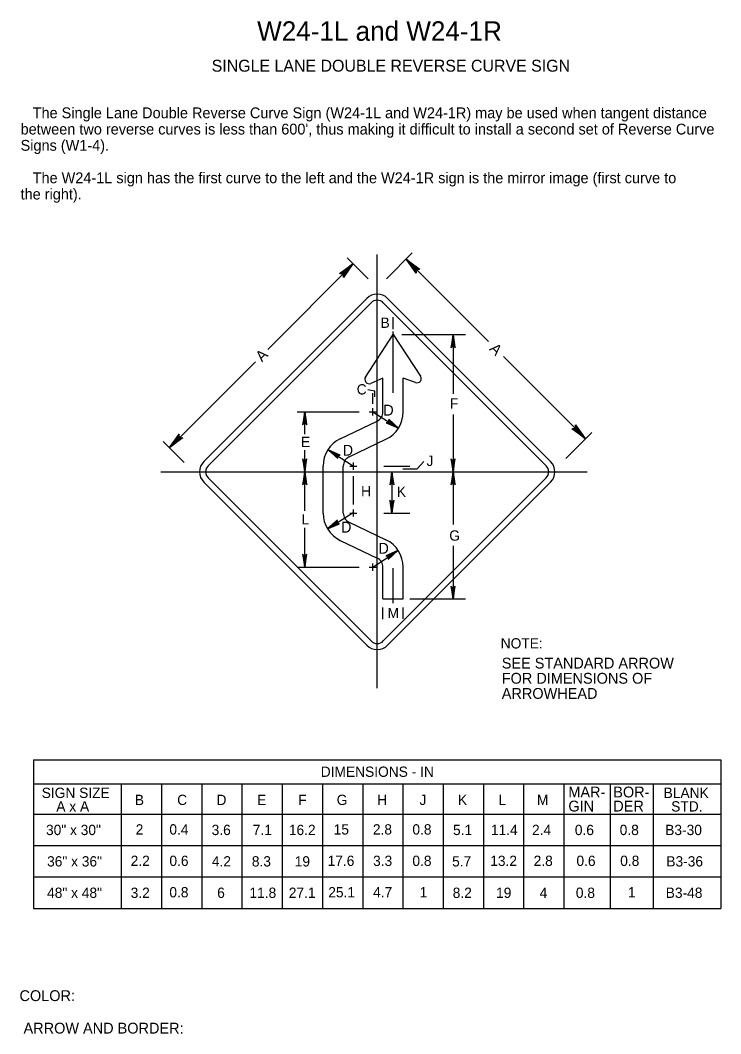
# Model space of a CAD drawing. Extents: x 0 to 0.249, y -0.213 to 0.259.
# Drawn here: x 0.0254 to 0.1872, y 0.0253 to 0.2592 of the extents above; entities that cross this region are included whole.
import ezdxf

# ---------------------------------------------------------------- set-up
doc = ezdxf.new("R2010")
doc.units = 0
for name, color, linetype in [('1', 7, 'Continuous'), ('2', 7, 'Continuous'), ('3', 7, 'Continuous')]:
    doc.layers.add(name, color=color, linetype=linetype)

# ---------------------------------------------------------------- blocks, each defined once
blk = doc.blocks.new('RARROW')
at = {"layer": '3'}
for p, q in [((-2.156, 0.28500000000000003), (-2.2665, 0.384625)), ((-2.2665, 0.384625), (0, 0)), ((0, 0), (-2.2665, -0.379125)), ((-2.156, 0.28500000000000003), (-2.075625, 0.12075)), ((0, 0), (-2.156, 0.28500000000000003)), ((-2.14975, -0.2705), (0, 0)), ((-2.075625, 0.12075), (0, 0)), ((0, 0), (-2.074, -0.108)), ((-2.2665, -0.379125), (-2.14975, -0.2705)), ((-2.074, -0.108), (-2.14975, -0.2705))]:
    blk.add_line(p, q, dxfattribs=at)

msp = doc.modelspace()

# ---------------------------------------------------------------- linework, layer by layer
at = {"layer": '1'}
for p, q in [((0.1051320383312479, 0.17690433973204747), (0.11151897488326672, 0.1866847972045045)), ((0.11151897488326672, 0.1866847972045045), (0.11786757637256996, 0.17711686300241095)), ((0.10918564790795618, 0.1766147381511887), (0.10635426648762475, 0.17543499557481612)), ((0.10918564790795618, 0.16885377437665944), (0.10918564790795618, 0.1766147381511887)), ((0.11385230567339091, 0.16885377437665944), (0.11385230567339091, 0.176643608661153)), ((0.11669363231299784, 0.17562884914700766), (0.11385230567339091, 0.176643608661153)), ((0.10601377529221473, 0.16885146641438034), (0.10768044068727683, 0.16885146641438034)), ((0.10684710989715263, 0.16801813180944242), (0.10684710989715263, 0.16968479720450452)), ((0.09932953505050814, 0.1626651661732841), (0.10785990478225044, 0.16674921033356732)), ((0.10134472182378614, 0.15845603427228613), (0.10987508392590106, 0.162540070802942)), ((0.1023523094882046, 0.15551813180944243), (0.1023523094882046, 0.1571847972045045)), ((0.09535231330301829, 0.14551652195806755), (0.09535231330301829, 0.15635146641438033)), ((0.1000189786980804, 0.14551651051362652), (0.1000189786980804, 0.15635147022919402)), ((0.1015189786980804, 0.15635146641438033), (0.10318564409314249, 0.15635146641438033)), ((0.1015189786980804, 0.14551813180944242), (0.10318564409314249, 0.14551813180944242)), ((0.1023523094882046, 0.14468479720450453), (0.1023523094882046, 0.14635146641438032)), ((0.10134552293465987, 0.14341156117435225), (0.10987266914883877, 0.13933307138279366)), ((0.09933194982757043, 0.1392016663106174), (0.10785910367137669, 0.13512317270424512)), ((0.10685250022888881, 0.13218479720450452), (0.10685250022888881, 0.13385146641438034)), ((0.10601916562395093, 0.1330181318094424), (0.10768583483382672, 0.1330181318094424)), ((0.10918564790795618, 0.12568479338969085), (0.10918564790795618, 0.13301821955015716)), ((0.11385230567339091, 0.12568479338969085), (0.11385230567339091, 0.1330182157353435)), ((0.10918564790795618, 0.12568479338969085), (0.11385230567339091, 0.12568479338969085))]:
    msp.add_line(p, q, dxfattribs=at)
for centre, radius, start, end in [((0.10596964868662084, 0.17635807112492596), 0.0009999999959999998, 146.8886580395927, 292.619864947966), ((0.11702996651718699, 0.17657059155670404), 0.0009999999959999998, 250.34617594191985, 33.111341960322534), ((0.10685231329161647, 0.16885377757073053), 0.002333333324, 295.58345846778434, 0), ((0.10685230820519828, 0.16885377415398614), 0.006999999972, 295.5834507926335, 0), ((0.10235231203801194, 0.15635147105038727), 0.006999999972, 115.58345385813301, 180), ((0.10235231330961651, 0.15635147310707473), 0.002333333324, 115.58343656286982, 180), ((0.10235231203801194, 0.14551652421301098), 0.006999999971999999, 180.00000000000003, 244.43845176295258), ((0.10235231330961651, 0.14551651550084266), 0.002333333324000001, 180, 244.43846100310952), ((0.10685230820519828, 0.13301821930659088), 0.006999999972, 0, 64.4384641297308), ((0.10685231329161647, 0.13301822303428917), 0.002333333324, 0, 64.43844982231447)]:
    msp.add_arc(centre, radius, start, end, dxfattribs=at)
at = {"layer": '3'}
for p, q in [((0.10573099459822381, 0.19956586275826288), (0.10088344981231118, 0.20441340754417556)), ((0.10785231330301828, 0.10509737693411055), (0.10785231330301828, 0.20518405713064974)), ((0.10997363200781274, 0.19956586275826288), (0.1159481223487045, 0.20554035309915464)), ((0.13353318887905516, 0.18512686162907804), (0.11453390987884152, 0.20412614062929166)), ((0.08259047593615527, 0.18329200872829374), (0.10229766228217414, 0.20299919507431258)), ((0.06783006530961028, 0.15742229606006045), (0.10544814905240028, 0.19504037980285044)), ((0.1102564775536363, 0.19504037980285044), (0.1478745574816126, 0.15742229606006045)), ((0.06882001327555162, 0.15643234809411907), (0.10643809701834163, 0.1940504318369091)), ((0.10926652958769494, 0.1940504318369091), (0.14688460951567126, 0.15643234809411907)), ((0.11151897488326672, 0.18795559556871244), (0.11151897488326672, 0.19074300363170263)), ((0.11151897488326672, 0.173223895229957), (0.11151897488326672, 0.18739218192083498)), ((0.1135189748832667, 0.1866847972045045), (0.12823541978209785, 0.1866847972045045)), ((0.1254354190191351, 0.17299726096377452), (0.1254354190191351, 0.1866847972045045)), ((0.05987125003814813, 0.1605727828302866), (0.07971428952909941, 0.18041582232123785)), ((0.15597037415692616, 0.16268968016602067), (0.13701492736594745, 0.18164512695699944)), ((0.10684710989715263, 0.17068479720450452), (0.10684710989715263, 0.17314034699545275)), ((0.1078524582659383, 0.17068479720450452), (0.1078524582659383, 0.17314034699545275)), ((0.08940579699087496, 0.16885146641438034), (0.10368564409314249, 0.16885146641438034)), ((0.09116848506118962, 0.16374726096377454), (0.09116848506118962, 0.16885146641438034)), ((0.10684710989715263, 0.16885146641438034), (0.11277511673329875, 0.1651227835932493)), ((0.1254354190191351, 0.15501813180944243), (0.1254354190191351, 0.16825729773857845)), ((0.1514100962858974, 0.15812940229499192), (0.15738458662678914, 0.16410389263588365)), ((0.06330458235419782, 0.1571394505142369), (0.058457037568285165, 0.16198699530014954)), ((0.09116848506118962, 0.15501813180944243), (0.09116848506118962, 0.15999726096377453)), ((0.09647811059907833, 0.1601585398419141), (0.1023523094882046, 0.15635146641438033)), ((0.057889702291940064, 0.15501813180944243), (0.1563329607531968, 0.15501813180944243)), ((0.09116848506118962, 0.14599726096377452), (0.09116848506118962, 0.15501813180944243)), ((0.10935231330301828, 0.15635146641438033), (0.11535231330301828, 0.15635146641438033)), ((0.10935231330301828, 0.1550236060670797), (0.11535231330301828, 0.1550236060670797)), ((0.11128743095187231, 0.14551813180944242), (0.11128743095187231, 0.15501813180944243)), ((0.1254354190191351, 0.14287226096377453), (0.1254354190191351, 0.15501813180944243)), ((0.10544814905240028, 0.11499588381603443), (0.06783006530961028, 0.15261396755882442)), ((0.10643809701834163, 0.11598583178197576), (0.06882001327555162, 0.15360391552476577)), ((0.1023523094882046, 0.14751813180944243), (0.1023523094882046, 0.15401813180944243)), ((0.14688460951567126, 0.15360391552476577), (0.10926652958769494, 0.11598583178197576)), ((0.1478745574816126, 0.15261396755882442), (0.1102564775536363, 0.11499588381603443)), ((0.09638502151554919, 0.1418570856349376), (0.10233118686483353, 0.14560599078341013)), ((0.10935231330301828, 0.14551813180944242), (0.11535231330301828, 0.14551813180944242)), ((0.09116848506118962, 0.1330181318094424), (0.09116848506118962, 0.14207527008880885)), ((0.10685250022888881, 0.1330181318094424), (0.11268459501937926, 0.13688919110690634)), ((0.1254354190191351, 0.12568479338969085), (0.1254354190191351, 0.13794160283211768)), ((0.08940579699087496, 0.1330181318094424), (0.10368564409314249, 0.1330181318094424)), ((0.11151897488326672, 0.1246955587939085), (0.11151897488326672, 0.13275243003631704)), ((0.11535230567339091, 0.12568479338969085), (0.12823541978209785, 0.12568479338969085)), ((0.10918564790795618, 0.12099726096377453), (0.10918564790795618, 0.12368479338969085)), ((0.11385230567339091, 0.12112226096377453), (0.11385230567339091, 0.12368479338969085)), ((0.028473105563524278, 0.08852774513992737), (0.028473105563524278, 0.05427774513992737)), ((0.028473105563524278, 0.08852774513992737), (0.18719164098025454, 0.08852774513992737)), ((0.18719164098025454, 0.08852774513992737), (0.18719164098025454, 0.05427774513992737)), ((0.028473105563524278, 0.08302774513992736), (0.18719164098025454, 0.08302774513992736)), ((0.04874079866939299, 0.08302774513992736), (0.04874079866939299, 0.05427774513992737)), ((0.058034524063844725, 0.08302774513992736), (0.058034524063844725, 0.05427774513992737)), ((0.06732824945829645, 0.08302774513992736), (0.06732824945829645, 0.05427774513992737)), ((0.0766219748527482, 0.08302774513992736), (0.0766219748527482, 0.05427774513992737)), ((0.08591570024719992, 0.08302774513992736), (0.08591570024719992, 0.05427774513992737)), ((0.09520942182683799, 0.08302774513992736), (0.09520942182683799, 0.05427774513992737)), ((0.10450314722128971, 0.08302774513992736), (0.10450314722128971, 0.05427774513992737)), ((0.11379687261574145, 0.08302774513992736), (0.11379687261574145, 0.05427774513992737)), ((0.12309059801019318, 0.08302774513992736), (0.12309059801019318, 0.05427774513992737)), ((0.13238432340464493, 0.08302774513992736), (0.13238432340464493, 0.05427774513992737)), ((0.14167804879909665, 0.08302774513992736), (0.14167804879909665, 0.05427774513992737)), ((0.15097177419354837, 0.08302774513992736), (0.15097177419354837, 0.05427774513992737)), ((0.16165319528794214, 0.08302774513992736), (0.16165319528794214, 0.05428061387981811)), ((0.1716178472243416, 0.08302774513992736), (0.1716178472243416, 0.05428061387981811)), ((0.028473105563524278, 0.07602774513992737), (0.18719164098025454, 0.07602774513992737)), ((0.028473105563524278, 0.06877774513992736), (0.18719164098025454, 0.06877774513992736)), ((0.028473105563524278, 0.06152774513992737), (0.18719164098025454, 0.06152774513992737)), ((0.028473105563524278, 0.05427774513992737), (0.18719164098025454, 0.05427774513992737))]:
    msp.add_line(p, q, dxfattribs=at)
for points in [[(0.10734068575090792, 0.17236952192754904), (0.10734068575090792, 0.17367061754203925), (0.10565875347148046, 0.17394008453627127)], [(0.11375935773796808, 0.1557271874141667), (0.11709001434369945, 0.1557271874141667), (0.11862031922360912, 0.15743765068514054)]]:
    msp.add_lwpolyline(points, dxfattribs=at)
for centre, radius, start, end in [((0.10785231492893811, 0.19263621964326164), 0.0034, 44.99999742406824, 135), ((0.10785231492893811, 0.19263621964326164), 0.002, 44.99999742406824, 135), ((0.070234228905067, 0.15501813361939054), 0.0034, 135.00000000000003, 225.00000000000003), ((0.14547039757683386, 0.15501813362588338), 0.0034000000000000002, 315.0000025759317, 44.99999726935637), ((0.070234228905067, 0.15501813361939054), 0.002, 135.00000000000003, 225.00000000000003), ((0.14547039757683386, 0.15501813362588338), 0.002, 315.0000025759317, 44.99999726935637), ((0.10785231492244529, 0.11740004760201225), 0.0034000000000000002, 225, 315.00000273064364), ((0.10785231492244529, 0.11740004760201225), 0.002, 225, 315.00000273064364)]:
    msp.add_arc(centre, radius, start, end, dxfattribs=at)

# ---------------------------------------------------------------- block references
for p, xscale, yscale, rotation in [((0.114625, 0.20400000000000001), 0.0016545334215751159, 0.0016366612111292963, 135.00000000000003), ((0.10225000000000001, 0.203), 0.0016545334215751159, 0.0016366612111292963, 44.999999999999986), ((0.12537500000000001, 0.186625), 0.0013236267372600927, -0.001309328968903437, 90), ((0.091125, 0.168875), 0.0013236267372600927, -0.001309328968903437, 90), ((0.11275, 0.165125), 0.0013236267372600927, -0.0013093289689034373, -32.937747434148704), ((0.155875, 0.16275), 0.0016545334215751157, 0.001636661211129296, -45), ((0.059875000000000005, 0.160625), 0.001654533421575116, 0.001636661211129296, -135), ((0.0965, 0.160125), 0.0013236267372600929, -0.001309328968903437, 146.65790015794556), ((0.091125, 0.155), 0.0013236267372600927, -0.001309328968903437, -90), ((0.12537500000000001, 0.155), 0.0013236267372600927, -0.001309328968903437, -90), ((0.091125, 0.155), 0.0013236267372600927, -0.001309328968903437, 90), ((0.11125, 0.155), 0.0013236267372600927, -0.001309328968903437, 90), ((0.12537500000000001, 0.155), 0.0013236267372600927, -0.001309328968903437, 90), ((0.11125, 0.1455), 0.0013236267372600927, -0.001309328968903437, -90), ((0.096375, 0.141875), 0.0013236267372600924, -0.001309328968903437, -147.979386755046), ((0.091125, 0.133), 0.0013236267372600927, -0.001309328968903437, -90), ((0.112625, 0.136875), 0.0013236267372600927, -0.0013093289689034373, 33.673578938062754), ((0.12537500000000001, 0.12562500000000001), 0.0013236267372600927, -0.001309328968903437, -90)]:
    msp.add_blockref('RARROW', p, dxfattribs=dict(at, xscale=xscale, yscale=yscale, rotation=rotation))

# ---------------------------------------------------------------- texts
at = {"layer": '1'}
for s, height, p in [('W24-1L and W24-1R', 0.0045000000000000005, (0.080125, 0.2545)), ('SINGLE LANE DOUBLE REVERSE CURVE SIGN', 0.00275025, (0.069625, 0.247375)), ('NOTE:', 0.0023752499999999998, (0.136375, 0.11425)), ('SEE STANDARD ARROW', 0.0024997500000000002, (0.136625, 0.109625)), ('FOR DIMENSIONS OF', 0.0024997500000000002, (0.136625, 0.106125)), ('ARROWHEAD', 0.0024997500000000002, (0.136625, 0.10262500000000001)), ('COLOR:', 0.0024997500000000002, (0.02525, 0.032875)), (' ARROW AND BORDER:', 0.0024997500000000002, (0.02525, 0.025375))]:
    msp.add_text(s, height=height, dxfattribs=at).set_placement(p)
at = {"layer": '2'}
for s, p in [('   The Single Lane Double Reverse Curve Sign (W24-1L and W24-1R) may be used when tangent distance', (0.025500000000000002, 0.23662525)), ("between two reverse curves is less than 600', thus making it difficult to install a second set of Reverse Curve ", (0.025500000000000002, 0.23287549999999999)), ('Signs (W1-4).', (0.025500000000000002, 0.22912575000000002)), ('   The W24-1L sign has the first curve to the left and the W24-1R sign is the mirror image (first curve to ', (0.025500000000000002, 0.22162625)), ('the right).', (0.025500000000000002, 0.2178765))]:
    msp.add_text(s, height=0.0024997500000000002, dxfattribs=at).set_placement(p)
at = {"layer": '3'}
for s, height, p in [('B', 0.0023752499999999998, (0.108625, 0.18825)), ('C', 0.0023752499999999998, (0.10312500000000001, 0.172875)), ('F', 0.0023752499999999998, (0.124625, 0.169625)), ('D', 0.0024997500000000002, (0.10925, 0.168)), ('E', 0.0023752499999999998, (0.09025, 0.16075)), ('D', 0.0024997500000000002, (0.099875, 0.15875)), ('J', 0.0023752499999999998, (0.11925000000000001, 0.15637500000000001)), ('H', 0.0023752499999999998, (0.104125, 0.149375)), ('K', 0.0023752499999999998, (0.112375, 0.14925)), ('L', 0.0023752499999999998, (0.090375, 0.142875)), ('D', 0.0024997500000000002, (0.0995, 0.14100000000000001)), ('G', 0.0023752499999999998, (0.1245, 0.139125)), ('D', 0.0024997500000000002, (0.108125, 0.136125)), ('M', 0.0023752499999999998, (0.11025, 0.12125)), ('DIMENSIONS - IN', 0.0023752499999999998, (0.09481659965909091, 0.084625)), ('SIGN SIZE', 0.0023752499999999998, (0.030375, 0.07975)), ('MAR-', 0.0024997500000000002, (0.152, 0.079875)), ('BOR-', 0.0024997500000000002, (0.162375, 0.079875)), ('BLANK', 0.0023752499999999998, (0.17400000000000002, 0.07975)), ('B', 0.0023752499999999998, (0.051875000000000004, 0.078125)), ('C', 0.0023752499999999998, (0.061656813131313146, 0.078125)), ('D', 0.0023752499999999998, (0.07074456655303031, 0.078125)), ('E', 0.0023752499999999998, (0.08012651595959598, 0.078125)), ('F', 0.0023752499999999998, (0.089625, 0.078125)), ('G', 0.0023752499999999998, (0.0985, 0.078125)), ('H', 0.0023752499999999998, (0.107875, 0.078125)), ('J', 0.0023752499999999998, (0.11762500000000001, 0.078125)), ('K', 0.0023752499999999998, (0.1265, 0.078125)), ('L', 0.0023752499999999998, (0.135875, 0.078125)), ('M', 0.0023752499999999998, (0.14475, 0.078125)), ('A x A', 0.0023752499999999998, (0.03375, 0.076625)), ('GIN', 0.0024997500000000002, (0.152, 0.076625)), ('DER', 0.0024997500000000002, (0.162375, 0.076625)), ('STD.', 0.0023752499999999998, (0.17575000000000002, 0.076625)), ('30" x 30"', 0.0023752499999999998, (0.03137041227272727, 0.07118737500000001)), ('2', 0.0023752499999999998, (0.05207353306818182, 0.07131237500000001)), ('0.4', 0.0023752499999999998, (0.05985699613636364, 0.07131237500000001)), ('3.6', 0.0023752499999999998, (0.0696185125, 0.07118737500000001)), ('7.1', 0.0023752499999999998, (0.07911539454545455, 0.07118737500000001)), ('16.2', 0.0023752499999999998, (0.08745020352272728, 0.07118737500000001)), ('15', 0.0023752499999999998, (0.09780517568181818, 0.07131237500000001)), ('2.8', 0.0023752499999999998, (0.10685555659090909, 0.07131237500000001)), ('0.8', 0.0023752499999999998, (0.1159805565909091, 0.07131237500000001)), ('5.1', 0.0023752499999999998, (0.12536539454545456, 0.07118737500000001)), ('11.4', 0.0023752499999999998, (0.13410315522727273, 0.07118737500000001)), ('2.4', 0.0023752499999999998, (0.14360699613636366, 0.07118737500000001)), ('0.6', 0.0023752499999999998, (0.1534935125, 0.07118737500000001)), ('0.8', 0.0023752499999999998, (0.16385555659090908, 0.07118737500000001)), ('B3-30', 0.0023752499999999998, (0.17437138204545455, 0.07118737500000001)), ('36" x 36"', 0.0023752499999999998, (0.03162041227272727, 0.063937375)), ('2.2', 0.0023752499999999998, (0.05091997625, 0.064062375)), ('0.6', 0.0023752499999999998, (0.059868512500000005, 0.064062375)), ('4.2', 0.0023752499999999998, (0.06966997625, 0.063937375)), ('8.3', 0.0023752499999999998, (0.0789030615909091, 0.063937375)), ('19', 0.0023752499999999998, (0.08880589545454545, 0.063937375)), ('17.6', 0.0023752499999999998, (0.09639873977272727, 0.064062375)), ('3.3', 0.0023752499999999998, (0.1069030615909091, 0.064062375)), ('0.8', 0.0023752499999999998, (0.1159805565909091, 0.064062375)), ('5.7', 0.0023752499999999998, (0.12515414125, 0.063937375)), ('13.2', 0.0023752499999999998, (0.13395020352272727, 0.064062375)), ('2.8', 0.0023752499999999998, (0.14398055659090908, 0.064062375)), ('0.6', 0.0023752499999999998, (0.1538685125, 0.064062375)), ('0.8', 0.0023752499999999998, (0.1639805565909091, 0.064062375)), ('B3-36', 0.0023752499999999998, (0.17462642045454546, 0.063937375)), ('48" x 48"', 0.0023752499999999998, (0.03162041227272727, 0.056687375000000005)), ('3.2', 0.0023752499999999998, (0.05091997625, 0.056687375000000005)), ('0.8', 0.0023752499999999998, (0.05985555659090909, 0.056812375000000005)), ('6', 0.0023752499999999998, (0.07089706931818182, 0.056687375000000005)), ('11.8', 0.0023752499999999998, (0.07835171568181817, 0.056687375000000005)), ('27.1', 0.0023752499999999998, (0.08742968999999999, 0.056687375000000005)), ('25.1', 0.0023752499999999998, (0.09655469, 0.056812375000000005)), ('4.7', 0.0023752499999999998, (0.10690414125, 0.056812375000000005)), ('1', 0.0023752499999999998, (0.11764395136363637, 0.056812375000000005)), ('8.2', 0.0023752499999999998, (0.12529497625, 0.056687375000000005)), ('19', 0.0023752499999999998, (0.13530589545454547, 0.056687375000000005)), ('4', 0.0023752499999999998, (0.14538555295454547, 0.056687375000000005)), ('0.8', 0.0023752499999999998, (0.1537305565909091, 0.056687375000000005)), ('1', 0.0023752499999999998, (0.16576895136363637, 0.056812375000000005)), ('B3-48', 0.0023752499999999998, (0.17448846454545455, 0.056687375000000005))]:
    msp.add_text(s, height=height, dxfattribs=at).set_placement(p)
for rotation, p in [(45, (0.08125, 0.18025)), (315, (0.133625, 0.18325))]:
    msp.add_text('A', height=0.0024997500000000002, rotation=rotation, dxfattribs=at).set_placement(p)

doc.saveas('drawing.dxf')
